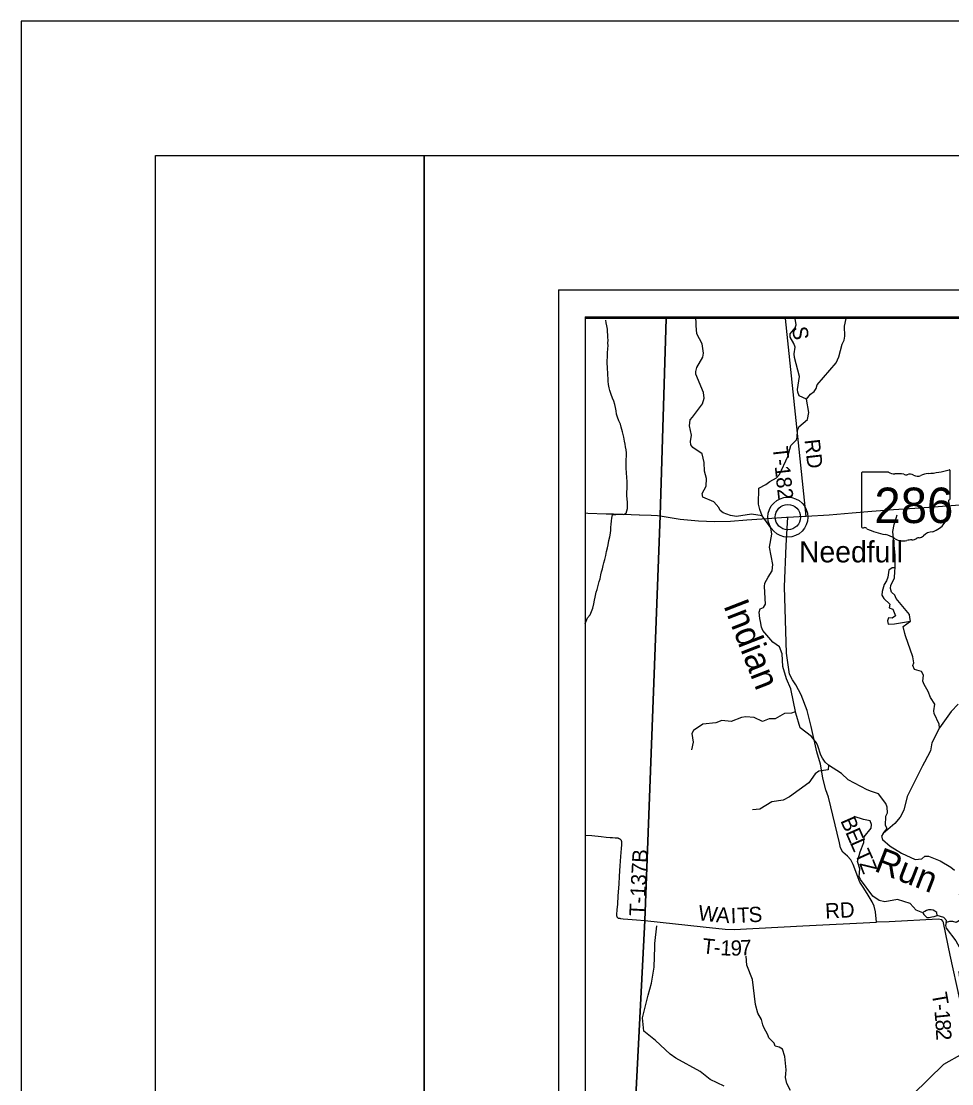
# Model space of a CAD drawing. Extents: x 0 to 34, y 0 to 22.
# Drawn here: x 0 to 3.465, y 18.045 to 22 of the extents above; entities that cross this region are included whole.
import ezdxf

# ---------------------------------------------------------------- set-up
doc = ezdxf.new("R2010")
doc.units = 0
for name, color, linetype in [('Default', 7, 'Continuous'), ('GM_X_County_Road', 7, 'Continuous'), ('GM_X_Minor_Lake', 7, 'Continuous'), ('GM_X_Minor_River', 7, 'Continuous'), ('GM_X_Minor_River_Text', 7, 'Continuous'), ('GM_X_State_Location', 7, 'Continuous'), ('GM_X_State_Route', 7, 'Continuous'), ('GM_X_State_Shield', 7, 'Continuous'), ('GM_X_Township_Road', 7, 'Continuous'), ('GM_X_Township_Road_Text', 7, 'Continuous'), ('GM_X_Unincorporated', 7, 'Continuous'), ('GM_X_Unincorporated_Location', 7, 'Continuous'), ('GM_X_Unincorporated_Text', 7, 'Continuous'), ('SH_Border', 7, 'Continuous'), ('SH_Cut_Line', 7, 'Continuous'), ('SH_Data', 7, 'Continuous')]:
    doc.layers.add(name, color=color, linetype=linetype)

msp = doc.modelspace()

# ---------------------------------------------------------------- linework, layer by layer
at = {"layer": 'Default'}
msp.add_lwpolyline([(2.4006, 20.8941), (2.1, 20.8941), (2.1, 14.637), (2.1837, 15.746), (2.258, 16.7775), (2.2632, 16.8811), (2.2668, 17.0936), (2.2797, 17.8302), (2.3212, 18.6531), (2.3791, 20.1601)], close=True, dxfattribs=at)
msp.add_lwpolyline([(6.7802, 17.4233), (6.9652, 18.9204), (7.0779, 19.8324), (7.1423, 20.3535), (7.155, 20.4756), (7.1718, 20.7748), (7.1725, 20.7885), (6.8666, 20.8494), (6.6419, 20.8941), (2.4006, 20.8941), (2.3791, 20.1601), (2.3212, 18.6531), (2.2797, 17.8302)], dxfattribs=at)
at = {"layer": 'GM_X_County_Road'}
msp.add_lwpolyline([(2.2799, 17.8297), (2.3457, 17.8058), (2.4145, 17.7838), (2.4313, 17.7804), (2.4446, 17.7777), (2.4762, 17.7775), (2.528, 17.7818), (2.592, 17.7876), (2.6324, 17.7878), (2.6933, 17.797), (2.8122, 17.8071), (2.9108, 17.8143), (3.0057, 17.8249), (3.0571, 17.8269), (3.0984, 17.8369), (3.1186, 17.8407), (3.1385, 17.8502), (3.1642, 17.8656), (3.218, 17.9056), (3.3195, 18.0053), (3.4349, 18.1181), (3.5055, 18.1584), (3.6368, 18.2427)], dxfattribs=at)
at = {"layer": 'GM_X_Minor_Lake'}
for points in [[(3.3089, 19.7807), (3.3068, 19.7925), (3.2577, 19.8518), (3.2527, 19.8644), (3.2407, 19.8756), (3.2364, 19.889), (3.2381, 19.9011), (3.2511, 19.9267), (3.2523, 19.9528), (3.2544, 19.9653), (3.2426, 19.9651), (3.2304, 19.957), (3.2269, 19.9305), (3.2221, 19.9173), (3.2124, 19.9042), (3.2051, 19.877), (3.2048, 19.8637), (3.2115, 19.8518), (3.2342, 19.831), (3.2321, 19.8173), (3.2457, 19.8122), (3.2504, 19.8), (3.2555, 19.7873), (3.2421, 19.7788), (3.2292, 19.7794), (3.2256, 19.7689), (3.2273, 19.756), (3.2512, 19.7578)], [(3.2512, 19.7578), (3.3104, 19.7676), (3.3089, 19.7807)], [(3.4104, 18.6717), (3.4091, 18.6831), (3.4016, 18.6882), (3.3948, 18.6909), (3.3873, 18.6933), (3.3785, 18.6927), (3.3701, 18.6902), (3.364, 18.6869), (3.3579, 18.6844), (3.3563, 18.6814), (3.36, 18.6752), (3.3652, 18.6702), (3.3716, 18.6637), (3.3803, 18.6646), (3.3906, 18.6664), (3.3986, 18.6677)], [(3.3986, 18.6677), (3.4104, 18.6717)]]:
    msp.add_lwpolyline(points, dxfattribs=at)
at = {"layer": 'GM_X_Minor_River'}
for points in [[(2.1838, 20.6939), (2.1832, 20.7038), (2.1826, 20.7133), (2.182, 20.7247), (2.1817, 20.7361), (2.1823, 20.7509), (2.1833, 20.7664), (2.1842, 20.7804), (2.1848, 20.7926), (2.1845, 20.8024), (2.1847, 20.8127), (2.1844, 20.8225), (2.1826, 20.8537), (2.1808, 20.8658), (2.1783, 20.8776), (2.1762, 20.8872)], [(2.7586, 20.1594), (2.7185, 20.1658), (2.663, 20.1569), (2.6407, 20.1599), (2.6135, 20.1698), (2.6027, 20.1791), (2.5976, 20.1898), (2.5786, 20.2118), (2.5379, 20.2284), (2.5347, 20.2422), (2.5504, 20.27), (2.5509, 20.2977), (2.5445, 20.3251), (2.5428, 20.3574), (2.5354, 20.3894), (2.5005, 20.4131), (2.4935, 20.4231), (2.4915, 20.436), (2.4953, 20.4599), (2.4875, 20.4941), (2.4906, 20.5169), (2.4991, 20.527), (2.5371, 20.5756), (2.5432, 20.5968), (2.5401, 20.6188), (2.5121, 20.6868), (2.5111, 20.6963), (2.5156, 20.7118), (2.5378, 20.7494), (2.5408, 20.7641), (2.5349, 20.7988), (2.5158, 20.837), (2.5133, 20.8674), (2.5124, 20.88), (2.5114, 20.8941)], [(3.2089, 18.9767), (3.224, 18.995), (3.2178, 19.0069), (3.2195, 19.0414), (3.2254, 19.0538), (3.2242, 19.075), (3.2196, 19.0891), (3.1917, 19.1241), (3.1657, 19.1333), (3.1491, 19.1393), (3.0784, 19.1762), (3.0542, 19.2001), (3.0062, 19.2309), (2.9935, 19.2421), (2.9835, 19.2567), (2.9769, 19.269), (2.9664, 19.3025), (2.9613, 19.3144), (2.9428, 19.3378), (2.9005, 19.3697), (2.8836, 19.425), (2.8658, 19.5152), (2.8494, 19.5527), (2.8354, 19.5988), (2.8328, 19.6459), (2.8226, 19.6711), (2.7983, 19.6886), (2.7615, 19.7321), (2.756, 19.7447), (2.7522, 19.7664), (2.7497, 19.7775), (2.7471, 19.8006), (2.7511, 19.8127), (2.7633, 19.8178), (2.7711, 19.8298), (2.767, 19.8967), (2.7691, 19.9084), (2.7812, 19.9306), (2.7953, 19.9539), (2.798, 19.9785), (2.7862, 20.042), (2.7942, 20.0908), (2.7908, 20.1144), (2.7586, 20.1594), (2.7495, 20.1827), (2.7453, 20.2032), (2.7463, 20.2617), (2.7728, 20.2764), (2.7866, 20.2864), (2.8126, 20.3), (2.8235, 20.3134), (2.8538, 20.3797), (2.8648, 20.4205), (2.8868, 20.4417), (2.8885, 20.4516), (2.8896, 20.4766), (2.8956, 20.4905), (2.9272, 20.5177), (2.9322, 20.5442), (2.9235, 20.5932), (2.8968, 20.6058), (2.8914, 20.6196), (2.8896, 20.6299), (2.8973, 20.6776), (2.8788, 20.7484), (2.8775, 20.7621), (2.881, 20.7867), (2.8763, 20.8001), (2.8634, 20.8242), (2.8633, 20.8367), (2.8819, 20.8592), (2.8847, 20.8701), (2.8818, 20.8941)], [(2.9235, 20.5932), (2.9383, 20.6116), (2.9517, 20.6216), (2.9603, 20.6336), (2.9631, 20.6468), (3.034, 20.7291), (3.0435, 20.7509), (3.0564, 20.7981), (3.0639, 20.8128), (3.0664, 20.8279), (3.0648, 20.8648), (3.0713, 20.8931), (3.0714, 20.8941)], [(2.1, 19.7582), (2.1034, 19.7674), (2.1089, 19.7795), (2.1177, 19.7907), (2.1236, 19.8035), (2.1283, 19.8152), (2.1319, 19.8319), (2.134, 19.8451), (2.1364, 19.8569), (2.1412, 19.8746), (2.1439, 19.8848), (2.1495, 19.9049), (2.1519, 19.9147), (2.1551, 19.9253), (2.1579, 19.9401), (2.1607, 19.9506), (2.1639, 19.962), (2.1667, 19.9741), (2.1691, 19.9839), (2.1727, 19.9971), (2.1763, 20.0119), (2.1791, 20.0267), (2.1823, 20.0403), (2.1847, 20.0512), (2.188, 20.0671), (2.192, 20.0811), (2.1936, 20.0944), (2.1946, 20.1054), (2.1958, 20.1167), (2.1967, 20.1273), (2.198, 20.1406), (2.1993, 20.1508), (2.2017, 20.1626), (2.2142, 20.1639), (2.2279, 20.1649), (2.2419, 20.1643), (2.2525, 20.1695), (2.2577, 20.1865), (2.2578, 20.1964), (2.2568, 20.2085), (2.2563, 20.2225), (2.2553, 20.2339), (2.2551, 20.2487), (2.2556, 20.2597), (2.2558, 20.2715), (2.2556, 20.2867), (2.2547, 20.3019), (2.2534, 20.3186), (2.2525, 20.3368), (2.2523, 20.3493), (2.2525, 20.3687), (2.2535, 20.3812), (2.2533, 20.3937), (2.2519, 20.4051), (2.2501, 20.4154), (2.2484, 20.426), (2.2466, 20.4374), (2.2434, 20.4519), (2.2413, 20.4621), (2.2388, 20.4724), (2.2341, 20.4896), (2.2308, 20.5002), (2.2253, 20.5132), (2.2202, 20.5265), (2.2169, 20.5372), (2.2145, 20.5494), (2.212, 20.5623), (2.2099, 20.5741), (2.2059, 20.5859), (2.2015, 20.597), (2.196, 20.6103), (2.1912, 20.6256), (2.1887, 20.6358), (2.187, 20.648), (2.1856, 20.6598), (2.185, 20.6704), (2.1841, 20.6833), (2.1838, 20.6939)], [(3.2544, 19.9653), (3.2541, 20.0116), (3.245, 20.1005), (3.2496, 20.127), (3.2576, 20.15), (3.2608, 20.1625)], [(3.419, 19.3706), (3.4173, 19.3839), (3.3994, 19.4229), (3.3973, 19.4332), (3.4011, 19.4578), (3.3853, 19.4824), (3.3773, 19.5049), (3.3614, 19.5309), (3.3567, 19.5443), (3.3594, 19.5663), (3.3524, 19.58), (3.326, 19.5877), (3.3198, 19.6015), (3.3238, 19.6124), (3.3192, 19.6349), (3.2921, 19.712), (3.2896, 19.7215), (3.284, 19.7474), (3.3104, 19.7676)], [(3.4884, 19.4582), (3.4625, 19.431), (3.419, 19.3706), (3.3907, 19.3146), (3.386, 19.2839), (3.3633, 19.2418), (3.3562, 19.2291), (3.2981, 19.1144), (3.2859, 19.0634), (3.2729, 19.037), (3.2532, 19.0135), (3.2089, 18.9767), (3.2034, 18.9669), (3.2062, 18.954), (3.235, 18.93), (3.2771, 18.9042), (3.3286, 18.8798), (3.3526, 18.882), (3.3641, 18.8928), (3.3778, 18.893), (3.4215, 18.8752), (3.4605, 18.851), (3.4744, 18.8409)], [(2.8836, 19.425), (2.8814, 19.4299), (2.868, 19.4249), (2.8418, 19.423), (2.807, 19.4039), (2.785, 19.4039), (2.7598, 19.3941), (2.7286, 19.4087), (2.6983, 19.4111), (2.6823, 19.4091), (2.6433, 19.3942), (2.6089, 19.3974), (2.586, 19.3887), (2.5374, 19.3843), (2.5024, 19.3606), (2.4962, 19.3485), (2.5017, 19.317), (2.4955, 19.2886)], [(3.0062, 19.2309), (3.0044, 19.2135), (2.9701, 19.2088), (2.9563, 19.1984), (2.9322, 19.165), (2.8608, 19.1128), (2.8374, 19.1014), (2.7948, 19.0942), (2.7496, 19.0673), (2.7226, 19.0654)], [(3.3563, 18.6814), (3.3326, 18.6912), (3.3099, 18.7163), (3.2623, 18.7307), (3.2159, 18.7228), (3.194, 18.727), (3.1712, 18.7433), (3.1244, 18.8055), (3.1204, 18.8162), (3.1228, 18.8454), (3.1142, 18.8725), (3.1235, 18.9083), (3.137, 18.9434), (3.1389, 18.9646), (3.1641, 18.9972), (3.1655, 19.0108), (3.1604, 19.0245), (3.1362, 19.0287), (3.1015, 19.0403)], [(3.4926, 18.7507), (3.5033, 18.7141), (3.5063, 18.6921), (3.5006, 18.6652), (3.4935, 18.6528), (3.4809, 18.6451), (3.4681, 18.6495), (3.4556, 18.6497), (3.4433, 18.645), (3.4416, 18.6348), (3.4441, 18.6245), (3.4801, 18.5772), (3.5059, 18.5302), (3.5117, 18.5164), (3.5155, 18.4963), (3.5119, 18.4827), (3.4992, 18.4734), (3.4903, 18.4614), (3.5033, 18.3543), (3.5119, 18.2768), (3.5107, 18.1647), (3.5113, 18.151), (3.5224, 18.1114), (3.4978, 18.0239)], [(3.4433, 18.645), (3.445, 18.6529), (3.4353, 18.6641), (3.4104, 18.6717)], [(2.6173, 18.036), (2.5653, 18.0607), (2.5399, 18.0813), (2.5283, 18.0909), (2.4373, 18.1406), (2.4155, 18.1558), (2.3621, 18.2063), (2.3184, 18.2412), (2.3135, 18.2913), (2.3346, 18.3751), (2.3464, 18.4192), (2.3561, 18.4793), (2.3585, 18.5547), (2.3595, 18.568), (2.3659, 18.6327)], [(2.8647, 18.02), (2.8499, 18.046), (2.8457, 18.0681), (2.8464, 18.0824), (2.8477, 18.0976), (2.8436, 18.1465), (2.8342, 18.1736), (2.8222, 18.181), (2.8067, 18.185), (2.8031, 18.1969), (2.783, 18.2165), (2.7801, 18.2276), (2.7646, 18.2547), (2.7614, 18.2643), (2.7564, 18.2844), (2.742, 18.3082), (2.7335, 18.3409), (2.7221, 18.4329), (2.7014, 18.4863), (2.6989, 18.5208)]]:
    msp.add_lwpolyline(points, dxfattribs=at)
at = {"layer": 'GM_X_State_Route'}
for points in [[(2.9228, 20.1585), (3.0082, 20.1632), (3.0935, 20.1705), (3.1668, 20.1769), (3.2472, 20.1824), (3.3269, 20.1872), (3.4134, 20.1937), (3.4946, 20.2), (3.5709, 20.2056), (3.6438, 20.2104), (3.7014, 20.2155), (3.7441, 20.2242)], [(2.1, 20.1698), (2.1094, 20.1695), (2.1775, 20.1672), (2.2054, 20.1663), (2.2395, 20.1652), (2.2708, 20.1643), (2.3003, 20.1632), (2.3019, 20.1631), (2.3458, 20.1612), (2.3688, 20.16), (2.3793, 20.1595)], [(2.3793, 20.1595), (2.4537, 20.1465), (2.5218, 20.1404), (2.5813, 20.1378), (2.6409, 20.1394), (2.702, 20.144), (2.7763, 20.1492), (2.8492, 20.154), (2.8547, 20.1544)], [(2.8547, 20.1544), (2.9179, 20.1582), (2.9228, 20.1585)]]:
    msp.add_lwpolyline(points, dxfattribs=at)
at = {"layer": 'GM_X_State_Shield'}
for p, q in [((3.4585, 20.2221), (3.4585, 20.3268)), ((3.1289, 20.3184), (3.1289, 20.1182)), ((3.2286, 20.3218), (3.1321, 20.3218)), ((3.4584, 20.2221), (3.4585, 20.2221))]:
    msp.add_line(p, q, dxfattribs=at)
for centre, major_axis, start_param, end_param in [((3.3411, 20.5946), (0.3495, 0), 4.814394, 5.042369), ((3.4548, 20.3272), (0.00367, 0), 6.141152, 7.989035), ((3.1327, 20.3188), (0.00382, 0), 1.712693, 3.28349), ((3.2516, 20.345), (0.037, 0), 4.042523, 4.731795), ((3.2639, 20.2094), (0.133, 0), 1.404758, 1.657858), ((3.2941, 20.3198), (0.0107, 0), 3.836095, 5.185415), ((3.3098, 20.2967), (0.0222, 0), 0.950623, 2.079405), ((3.3384, 20.3284), (0.0267, 0), 4.081561, 5.145723), ((3.3856, 20.2607), (0.0703, 0), 1.699011, 2.107814), ((3.4576, 20.2144), (0.00568, 0), 1.883978, 3.671073), ((3.4215, 20.2012), (0.0341, 0), 5.934695, 6.695948), ((3.4545, 20.2217), (0.00393, 0), 5.05454, 6.418171), ((3.3606, 20.1649), (0.0874, 0), 5.101752, 6.440018), ((3.4716, 20.1783), (0.0248, 0), 2.387724, 3.262537), ((3.1327, 20.1178), (0.00385, 0), 3.00124, 4.508301), ((3.1333, 20.1383), (0.0294, 0), 4.665946, 4.897461), ((3.1393, 20.1067), (0.0106, 0), 0.519207, 1.627899), ((3.2731, 20.2865), (0.2524, 0), 4.195997, 4.488961), ((3.1979, 20.0283), (0.079, 0), 0.823519, 1.323587), ((3.3975, 20.062), (0.0479, 0), 1.647645, 2.488434), ((3.2833, 20.1057), (0.0501, 0), 4.026481, 4.996735), ((3.3122, 20.0365), (0.0412, 0), 1.495662, 1.94098), ((3.3159, 20.0907), (0.0267, 0), 4.691044, 5.507374), ((3.34, 20.0713), (0.00752, 0), 1.147584, 2.315152), ((3.3368, 20.0988), (0.0282, 0), 4.937069, 5.64225)]:
    msp.add_ellipse(centre, major_axis=major_axis, ratio=0.8, start_param=start_param, end_param=end_param, dxfattribs=at)
at = {"layer": 'GM_X_Township_Road'}
msp.add_line((2.9228, 20.1585), (2.845, 20.8941), dxfattribs=at)
for points in [[(3.4338, 18.6449), (3.4336, 18.6458), (3.4309, 18.6508), (3.4279, 18.6553), (3.4142, 18.6581), (3.231, 18.6486), (3.1842, 18.6465), (3.1802, 18.6849), (3.1757, 18.7062), (3.1678, 18.7229), (3.153, 18.7477), (3.1368, 18.7728), (3.1228, 18.796), (3.0969, 18.8615), (3.0886, 18.8786), (3.0761, 18.892), (3.059, 18.9076), (3.0507, 18.9236), (3.0466, 18.9415), (3.0052, 19.1122), (2.9951, 19.1392), (2.9843, 19.183), (2.9829, 19.1917), (2.9758, 19.2354), (2.9616, 19.2811), (2.9407, 19.3746), (2.9258, 19.4344), (2.9044, 19.493), (2.8844, 19.5307), (2.8712, 19.5486), (2.8606, 19.5695), (2.8488, 19.6475), (2.8421, 19.8945), (2.8475, 20.0483), (2.8547, 20.1544)], [(2.8547, 20.1544), (2.9179, 20.1582), (2.9228, 20.1585)], [(2.2202, 18.664), (2.2197, 18.6646), (2.2191, 18.6656), (2.2187, 18.6666), (2.2183, 18.6676), (2.2179, 18.6688), (2.2176, 18.6702), (2.2174, 18.6715), (2.2174, 18.6729), (2.2174, 18.674), (2.2174, 18.6753), (2.2189, 18.6921), (2.2209, 18.7137), (2.2229, 18.7447), (2.2259, 18.7887), (2.2278, 18.8185), (2.2305, 18.8569), (2.2329, 18.891), (2.2348, 18.9214), (2.2357, 18.9345), (2.236, 18.9413), (2.236, 18.9429), (2.236, 18.9445), (2.2358, 18.9456), (2.2356, 18.9469), (2.2352, 18.948), (2.2349, 18.9492), (2.2344, 18.9503), (2.2336, 18.9517), (2.2327, 18.9529), (2.232, 18.9537), (2.2311, 18.9546), (2.2301, 18.9554), (2.229, 18.9562), (2.2279, 18.9569), (2.2268, 18.9574), (2.2254, 18.958), (2.224, 18.9584), (2.2221, 18.9589), (2.2205, 18.9592), (2.2184, 18.9595), (2.215, 18.9597), (2.2109, 18.9599), (2.2017, 18.9605), (2.1921, 18.9612), (2.1773, 18.9624), (2.1596, 18.9641), (2.1243, 18.9676), (2.1, 18.9697)], [(2.2202, 18.664), (2.221, 18.6634), (2.2219, 18.6629), (2.223, 18.6623), (2.2242, 18.6618), (2.2254, 18.6615), (2.2267, 18.6613), (2.2281, 18.6611), (2.2312, 18.6607), (2.2417, 18.6597), (2.2584, 18.6584), (2.2912, 18.6554), (2.3214, 18.6525)], [(2.3214, 18.6525), (2.5387, 18.6296), (2.6209, 18.6212), (2.6547, 18.62), (2.9103, 18.6333), (3.1842, 18.6465)], [(3.5055, 18.1584), (3.5044, 18.2522), (3.5005, 18.3031), (3.4946, 18.3597), (3.4589, 18.5238), (3.4338, 18.6449)]]:
    msp.add_lwpolyline(points, dxfattribs=at)
at = {"layer": 'GM_X_Unincorporated'}
for radius in [0.0744, 0.0472]:
    msp.add_circle((2.8544, 20.1543), radius, dxfattribs=at)
at = {"layer": 'GM_X_Unincorporated_Location'}
msp.add_line((2.8544, 20.1543), (2.8544, 20.1543), dxfattribs=at)
at = {"layer": 'SH_Border'}
for points in [[(0.5, 21.5), (1.5, 21.5), (1.5, 0.5), (0.5, 0.5)], [(1.5, 21.5), (33.5, 21.5), (33.5, 0.5), (1.5, 0.5)]]:
    msp.add_lwpolyline(points, close=True, dxfattribs=at)
at = {"layer": 'SH_Cut_Line'}
for points in [[(0, 0), (34, 0), (34, 22), (0, 22)], [(2.4006, 20.8941), (2.1, 20.8941), (2.1, 14.637), (2.1837, 15.746), (2.258, 16.7775), (2.2632, 16.8811), (2.2668, 17.0936), (2.2797, 17.8302), (2.3212, 18.6531), (2.3791, 20.1601)]]:
    msp.add_lwpolyline(points, close=True, dxfattribs=at)
msp.add_lwpolyline([(8.9, 14.2922), (8.9, 20.8941), (2.4006, 20.8941), (2.3791, 20.1601), (2.3212, 18.6531), (2.2797, 17.8302)], dxfattribs=at)
at = {"layer": 'SH_Data'}
for p, q in [((2, 21), (9, 21)), ((2, 21), (2, 14)), ((2.1, 20.9), (2.1, 14.1)), ((2.1, 20.9), (8.9, 20.9))]:
    msp.add_line(p, q, dxfattribs=at)

# ---------------------------------------------------------------- texts
at = {"layer": 'GM_X_Minor_River_Text'}
for s, rotation, p in [('Indian', 291.2766, (2.6134, 19.8257)), ('Run', 338.6677, (3.1717, 18.8387))]:
    msp.add_text(s, height=0.0947, rotation=rotation, dxfattribs=at).set_placement(p)
at = {"layer": 'GM_X_State_Location'}
msp.add_text('286', height=0.000189, rotation=0, dxfattribs=at).set_placement((3.2231, 20.1912))
for s in ['s', 'r']:
    msp.add_text(s, height=0.000189, dxfattribs=at).set_placement((3.29, 20.205))
at = {"layer": 'GM_X_State_Shield'}
msp.add_text('286', height=0.13184, dxfattribs=at).set_placement((3.1763, 20.1323))
at = {"layer": 'GM_X_Township_Road_Text'}
for s, height, rotation, p in [('S', 0.0568, 276.733, (2.8704, 20.8613)), ('T-182', 0.05682, 276.1851, (2.7976, 20.4145)), ('RD', 0.05682, 276.3946, (2.9162, 20.4417)), ('B', 0.0568, 293.5737, (3.0488, 19.0246)), ('E', 0.0568, 293.5744, (3.0674, 18.9818)), ('L', 0.0568, 293.6362, (3.0845, 18.9428)), ('T-137B', 0.05682, 86.9739, (2.3202, 18.6683)), ('T', 0.0568, 294.396, (3.1018, 18.9031)), ('Z', 0.0568, 291.5824, (3.1191, 18.8651)), ('W', 0.0568, 353.4426, (2.5182, 18.6547)), ('S', 0.0568, 3.3933, (2.7099, 18.6458)), ('RD', 0.05682, 2.9593, (2.9945, 18.6599)), ('A', 0.0568, 355.39, (2.5857, 18.647)), ('I', 0.0568, 1.3624, (2.642, 18.6428)), ('T', 0.0568, 3.1637, (2.6672, 18.6434)), ('T', 0.0568, 353.834, (2.5333, 18.5312)), ('-', 0.0568, 354.2572, (2.576, 18.5266)), ('1', 0.0568, 356.4399, (2.6016, 18.5241)), ('9', 0.0568, 1.3794, (2.6418, 18.5218)), ('7', 0.0568, 3.1378, (2.6787, 18.5227)), ('T', 0.0568, 280.0887, (3.3897, 18.3807)), ('1', 0.0568, 275.3851, (3.3997, 18.3169)), ('-', 0.0568, 276.6128, (3.3971, 18.3398)), ('8', 0.0568, 274.4694, (3.403, 18.2823)), ('2', 0.0568, 272.0209, (3.4057, 18.2481))]:
    msp.add_text(s, height=height, rotation=rotation, dxfattribs=at).set_placement(p)
at = {"layer": 'GM_X_Unincorporated_Text'}
msp.add_text('Needfull', height=0.07898, rotation=0, dxfattribs=at).set_placement((2.8956, 19.9859))

doc.saveas('drawing.dxf')
